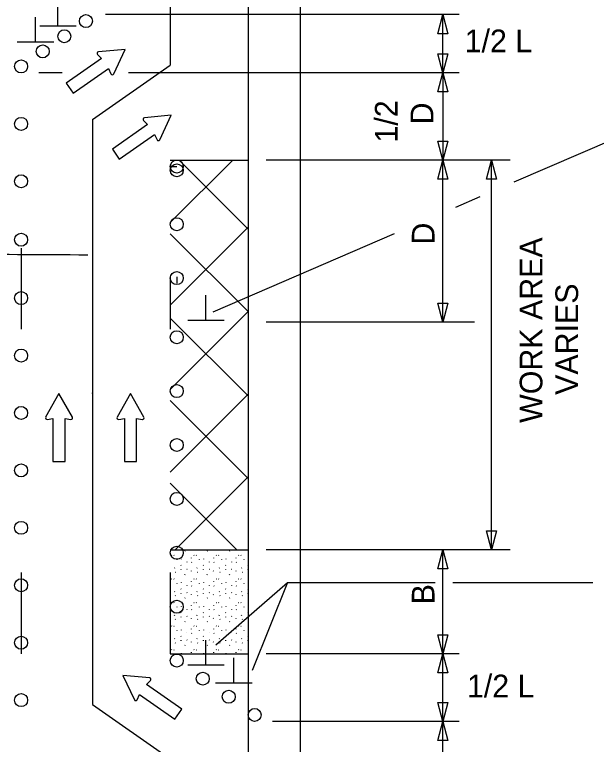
# Model space of a CAD drawing. Extents: x 16577 to 18475, y 5712 to 6919.
# Drawn here: x 16970.7 to 17150.1, y 6431 to 6656 of the extents above; entities that cross this region are included whole.
import ezdxf

# ---------------------------------------------------------------- set-up
doc = ezdxf.new("R2010")
doc.units = 0
for name, color, linetype in [('ALI_LEGAL_EX', 7, 'Continuous'), ('MT_SCRATCH_LEVEL_A', 7, 'Continuous'), ('MT_SCRATCH_LEVEL_E', 7, 'Continuous'), ('PAVT_EDGE_EX', 7, 'Continuous'), ('TRAFFIC_SIGNS_PR', 7, 'Continuous'), ('TYPICAL_TEXT_DIMEN_PR', 7, 'Continuous')]:
    doc.layers.add(name, color=color, linetype=linetype)

msp = doc.modelspace()

# ---------------------------------------------------------------- linework, layer by layer
at = {"layer": 'ALI_LEGAL_EX'}
for points in [[(16972.75, 6583.94), (16972.75, 6558.94)], [(17018.75, 6575.12), (17018.75, 6558.94)], [(17020.75, 6575.12), (17020.75, 6573.12)], [(16972.75, 6483.94), (16972.75, 6458.94)], [(17018.75, 6483.94), (17018.75, 6458.94)]]:
    msp.add_lwpolyline(points, dxfattribs=at)
at = {"layer": 'MT_SCRATCH_LEVEL_A'}
for p, q in [((17018.75, 6611.12), (17042.75, 6611.12)), ((17018.75, 6591.85), (17038.01, 6611.12)), ((17042.75, 6589.86), (17021.49, 6611.12)), ((17018.75, 6609.12), (17020.75, 6609.12)), ((17018.75, 6566.4), (17042.75, 6590.4)), ((17042.75, 6564.4), (17018.75, 6588.4)), ((17018.75, 6540.4), (17042.75, 6564.4)), ((17042.75, 6538.4), (17018.75, 6562.4)), ((17018.75, 6514.94), (17042.75, 6538.94)), ((17042.75, 6512.95), (17018.75, 6536.95)), ((17020.21, 6490.94), (17042.75, 6513.49)), ((17039.3, 6490.94), (17018.75, 6511.49)), ((17018.75, 6490.94), (17042.75, 6490.94)), ((17023.23, 6490.59), (17023.28, 6490.7)), ((17030.11, 6490.59), (17030.17, 6490.7)), ((17037, 6490.59), (17037.05, 6490.7)), ((17019.12, 6489.35), (17019.17, 6489.27)), ((17019.86, 6489.32), (17019.91, 6489.24)), ((17025.25, 6488.39), (17025.3, 6488.51)), ((17026.01, 6489.35), (17026.06, 6489.27)), ((17026.75, 6489.32), (17026.8, 6489.24)), ((17032.13, 6488.39), (17032.19, 6488.51)), ((17032.9, 6489.35), (17032.95, 6489.27)), ((17033.64, 6489.32), (17033.69, 6489.24)), ((17039.02, 6488.39), (17039.07, 6488.51)), ((17039.78, 6489.35), (17039.84, 6489.27)), ((17040.52, 6489.32), (17040.57, 6489.24)), ((17020.73, 6487.94), (17020.78, 6487.86)), ((17022.01, 6486.2), (17022.06, 6486.13)), ((17022.18, 6488.09), (17022.23, 6488.21)), ((17023.8, 6487.26), (17023.85, 6487.19)), ((17025.33, 6487.12), (17025.38, 6487.05)), ((17027.62, 6487.94), (17027.67, 6487.86)), ((17028.89, 6486.2), (17028.94, 6486.13)), ((17029.06, 6488.09), (17029.12, 6488.21)), ((17030.68, 6487.26), (17030.74, 6487.19)), ((17032.21, 6487.12), (17032.26, 6487.05)), ((17034.5, 6487.94), (17034.56, 6487.86)), ((17035.78, 6486.2), (17035.83, 6486.13)), ((17035.95, 6488.09), (17036, 6488.21)), ((17037.57, 6487.26), (17037.62, 6487.19)), ((17039.1, 6487.12), (17039.15, 6487.05)), ((17041.39, 6487.94), (17041.44, 6487.86)), ((17042.67, 6486.2), (17042.72, 6486.13)), ((17020.08, 6485.33), (17020.13, 6485.45)), ((17020.27, 6484.13), (17020.32, 6484.06)), ((17022.05, 6484.8), (17022.1, 6484.92)), ((17023.85, 6485.05), (17023.9, 6484.98)), ((17025.13, 6484.48), (17025.14, 6484.36)), ((17026.97, 6485.33), (17027.02, 6485.45)), ((17027.16, 6484.13), (17027.21, 6484.06)), ((17028.94, 6484.8), (17028.99, 6484.92)), ((17030.73, 6485.05), (17030.78, 6484.98)), ((17032.01, 6484.48), (17032.03, 6484.36)), ((17033.85, 6485.33), (17033.91, 6485.45)), ((17034.04, 6484.13), (17034.1, 6484.06)), ((17035.82, 6484.8), (17035.88, 6484.92)), ((17037.62, 6485.05), (17037.67, 6484.98)), ((17038.9, 6484.48), (17038.91, 6484.36)), ((17040.74, 6485.33), (17040.8, 6485.45)), ((17040.93, 6484.13), (17040.98, 6484.06)), ((17042.71, 6484.8), (17042.76, 6484.92)), ((17019.12, 6482.06), (17019.17, 6481.99)), ((17019.86, 6482.03), (17019.91, 6481.96)), ((17023.23, 6483.3), (17023.28, 6483.42)), ((17026.01, 6482.06), (17026.06, 6481.99)), ((17026.75, 6482.03), (17026.8, 6481.96)), ((17030.11, 6483.3), (17030.17, 6483.42)), ((17032.9, 6482.06), (17032.95, 6481.99)), ((17033.64, 6482.03), (17033.69, 6481.96)), ((17037, 6483.3), (17037.05, 6483.42)), ((17039.78, 6482.06), (17039.84, 6481.99)), ((17040.52, 6482.03), (17040.57, 6481.96)), ((17020.73, 6480.65), (17020.78, 6480.58)), ((17022.18, 6480.81), (17022.23, 6480.92)), ((17023.8, 6479.98), (17023.85, 6479.9)), ((17025.25, 6481.1), (17025.3, 6481.22)), ((17025.33, 6479.84), (17025.38, 6479.76)), ((17027.62, 6480.65), (17027.67, 6480.58)), ((17029.06, 6480.81), (17029.12, 6480.92)), ((17030.68, 6479.98), (17030.74, 6479.9)), ((17032.13, 6481.1), (17032.19, 6481.22)), ((17032.21, 6479.84), (17032.26, 6479.76)), ((17034.5, 6480.65), (17034.56, 6480.58)), ((17035.95, 6480.81), (17036, 6480.92)), ((17037.57, 6479.98), (17037.62, 6479.9)), ((17039.02, 6481.1), (17039.07, 6481.22)), ((17039.1, 6479.84), (17039.15, 6479.76)), ((17041.39, 6480.65), (17041.44, 6480.58)), ((17020.08, 6478.05), (17020.13, 6478.16)), ((17022.01, 6478.92), (17022.06, 6478.84)), ((17022.05, 6477.52), (17022.1, 6477.64)), ((17023.85, 6477.77), (17023.9, 6477.69)), ((17025.13, 6477.19), (17025.14, 6477.08)), ((17026.97, 6478.05), (17027.02, 6478.16)), ((17028.89, 6478.92), (17028.94, 6478.84)), ((17028.94, 6477.52), (17028.99, 6477.64)), ((17030.73, 6477.77), (17030.78, 6477.69)), ((17032.01, 6477.19), (17032.03, 6477.08)), ((17033.85, 6478.05), (17033.91, 6478.16)), ((17035.78, 6478.92), (17035.83, 6478.84)), ((17035.82, 6477.52), (17035.88, 6477.64)), ((17037.62, 6477.77), (17037.67, 6477.69)), ((17038.9, 6477.19), (17038.91, 6477.08)), ((17040.74, 6478.05), (17040.8, 6478.16)), ((17042.67, 6478.92), (17042.72, 6478.84)), ((17042.71, 6477.52), (17042.76, 6477.64)), ((17020.27, 6476.85), (17020.32, 6476.77)), ((17023.23, 6476.02), (17023.28, 6476.13)), ((17027.16, 6476.85), (17027.21, 6476.77)), ((17030.11, 6476.02), (17030.17, 6476.13)), ((17034.04, 6476.85), (17034.1, 6476.77)), ((17037, 6476.02), (17037.05, 6476.13)), ((17040.93, 6476.85), (17040.98, 6476.77)), ((17019.12, 6474.78), (17019.17, 6474.7)), ((17019.86, 6474.75), (17019.91, 6474.67)), ((17020.73, 6473.37), (17020.78, 6473.29)), ((17022.18, 6473.52), (17022.23, 6473.64)), ((17023.8, 6472.69), (17023.85, 6472.62)), ((17025.25, 6473.82), (17025.3, 6473.94)), ((17025.33, 6472.55), (17025.38, 6472.48)), ((17026.01, 6474.78), (17026.06, 6474.7)), ((17026.75, 6474.75), (17026.8, 6474.67)), ((17027.62, 6473.37), (17027.67, 6473.29)), ((17029.06, 6473.52), (17029.12, 6473.64)), ((17030.68, 6472.69), (17030.74, 6472.62)), ((17032.13, 6473.82), (17032.19, 6473.94)), ((17032.21, 6472.55), (17032.26, 6472.48)), ((17032.9, 6474.78), (17032.95, 6474.7)), ((17033.64, 6474.75), (17033.69, 6474.67)), ((17034.5, 6473.37), (17034.56, 6473.29)), ((17035.95, 6473.52), (17036, 6473.64)), ((17037.57, 6472.69), (17037.62, 6472.62)), ((17039.02, 6473.82), (17039.07, 6473.94)), ((17039.1, 6472.55), (17039.15, 6472.48)), ((17039.78, 6474.78), (17039.84, 6474.7)), ((17040.52, 6474.75), (17040.57, 6474.67)), ((17041.39, 6473.37), (17041.44, 6473.29)), ((17020.08, 6470.76), (17020.13, 6470.88)), ((17022.01, 6471.63), (17022.06, 6471.56)), ((17022.05, 6470.23), (17022.1, 6470.35)), ((17023.85, 6470.48), (17023.9, 6470.41)), ((17026.97, 6470.76), (17027.02, 6470.88)), ((17028.89, 6471.63), (17028.94, 6471.56)), ((17028.94, 6470.23), (17028.99, 6470.35)), ((17030.73, 6470.48), (17030.78, 6470.41)), ((17033.85, 6470.76), (17033.91, 6470.88)), ((17035.78, 6471.63), (17035.83, 6471.56)), ((17035.82, 6470.23), (17035.88, 6470.35)), ((17037.62, 6470.48), (17037.67, 6470.41)), ((17040.74, 6470.76), (17040.8, 6470.88)), ((17042.67, 6471.63), (17042.72, 6471.56)), ((17042.71, 6470.23), (17042.76, 6470.35)), ((17020.27, 6469.57), (17020.32, 6469.49)), ((17023.23, 6468.73), (17023.28, 6468.85)), ((17025.13, 6469.91), (17025.14, 6469.79)), ((17027.16, 6469.57), (17027.21, 6469.49)), ((17030.11, 6468.73), (17030.17, 6468.85)), ((17032.01, 6469.91), (17032.03, 6469.79)), ((17034.04, 6469.57), (17034.1, 6469.49)), ((17037, 6468.73), (17037.05, 6468.85)), ((17038.9, 6469.91), (17038.91, 6469.79)), ((17040.93, 6469.57), (17040.98, 6469.49)), ((17019.12, 6467.49), (17019.17, 6467.42)), ((17019.86, 6467.47), (17019.91, 6467.39)), ((17020.73, 6466.09), (17020.78, 6466.01)), ((17022.18, 6466.24), (17022.23, 6466.35)), ((17025.25, 6466.53), (17025.3, 6466.65)), ((17026.01, 6467.49), (17026.06, 6467.42)), ((17026.75, 6467.47), (17026.8, 6467.39)), ((17027.62, 6466.09), (17027.67, 6466.01)), ((17029.06, 6466.24), (17029.12, 6466.35)), ((17032.13, 6466.53), (17032.19, 6466.65)), ((17032.9, 6467.49), (17032.95, 6467.42)), ((17033.64, 6467.47), (17033.69, 6467.39)), ((17034.5, 6466.09), (17034.56, 6466.01)), ((17035.95, 6466.24), (17036, 6466.35)), ((17039.02, 6466.53), (17039.07, 6466.65)), ((17039.78, 6467.49), (17039.84, 6467.42)), ((17040.52, 6467.47), (17040.57, 6467.39)), ((17041.39, 6466.09), (17041.44, 6466.01)), ((17020.08, 6463.48), (17020.13, 6463.6)), ((17022.01, 6464.35), (17022.06, 6464.27)), ((17023.8, 6465.41), (17023.85, 6465.33)), ((17025.33, 6465.27), (17025.38, 6465.19)), ((17026.97, 6463.48), (17027.02, 6463.6)), ((17028.89, 6464.35), (17028.94, 6464.27)), ((17030.68, 6465.41), (17030.74, 6465.33)), ((17032.21, 6465.27), (17032.26, 6465.19)), ((17033.85, 6463.48), (17033.91, 6463.6)), ((17035.78, 6464.35), (17035.83, 6464.27)), ((17037.57, 6465.41), (17037.62, 6465.33)), ((17039.1, 6465.27), (17039.15, 6465.19)), ((17040.74, 6463.48), (17040.8, 6463.6)), ((17042.67, 6464.35), (17042.72, 6464.27)), ((17020.27, 6462.28), (17020.32, 6462.2)), ((17022.05, 6462.95), (17022.1, 6463.07)), ((17023.23, 6461.45), (17023.28, 6461.56)), ((17023.85, 6463.2), (17023.9, 6463.12)), ((17025.13, 6462.62), (17025.14, 6462.51)), ((17027.16, 6462.28), (17027.21, 6462.2)), ((17028.94, 6462.95), (17028.99, 6463.07)), ((17030.11, 6461.45), (17030.17, 6461.56)), ((17030.73, 6463.2), (17030.78, 6463.12)), ((17032.01, 6462.62), (17032.03, 6462.51)), ((17034.04, 6462.28), (17034.1, 6462.2)), ((17035.82, 6462.95), (17035.88, 6463.07)), ((17037, 6461.45), (17037.05, 6461.56)), ((17037.62, 6463.2), (17037.67, 6463.12)), ((17038.9, 6462.62), (17038.91, 6462.51)), ((17040.93, 6462.28), (17040.98, 6462.2)), ((17042.71, 6462.95), (17042.76, 6463.07)), ((17019.12, 6460.21), (17019.17, 6460.13)), ((17019.86, 6460.18), (17019.91, 6460.1)), ((17022.18, 6458.95), (17022.23, 6459.07)), ((17025.25, 6459.25), (17025.3, 6459.37)), ((17026.01, 6460.21), (17026.06, 6460.13)), ((17026.75, 6460.18), (17026.8, 6460.1)), ((17029.06, 6458.95), (17029.12, 6459.07)), ((17032.13, 6459.25), (17032.19, 6459.37)), ((17032.9, 6460.21), (17032.95, 6460.13)), ((17033.64, 6460.18), (17033.69, 6460.1)), ((17035.95, 6458.95), (17036, 6459.07)), ((17039.02, 6459.25), (17039.07, 6459.37)), ((17039.78, 6460.21), (17039.84, 6460.13)), ((17040.52, 6460.18), (17040.57, 6460.1)), ((17018.75, 6458.89), (17042.75, 6458.89))]:
    msp.add_line(p, q, dxfattribs=at)
at = {"layer": 'MT_SCRATCH_LEVEL_E'}
for p, q in [((16996.28, 6643.67), (16997.56, 6642.4)), ((16996.28, 6643.67), (16997.56, 6642.4)), ((17004.86, 6645.23), (16996.57, 6644.46)), ((17004.86, 6645.23), (16996.57, 6644.46)), ((17001.3, 6637.69), (17004.86, 6645.23)), ((17001.3, 6637.69), (17004.86, 6645.23)), ((16997.56, 6642.4), (16986.69, 6634.8)), ((16997.56, 6642.4), (16986.69, 6634.8)), ((16988.83, 6631.74), (16999.7, 6639.33)), ((16988.83, 6631.74), (16999.7, 6639.33)), ((16999.7, 6639.33), (17000.46, 6637.69)), ((16999.7, 6639.33), (17000.46, 6637.69)), ((16986.69, 6634.8), (16988.83, 6631.74)), ((16986.69, 6634.8), (16988.83, 6631.74)), ((17010.48, 6623.35), (17011.75, 6622.07)), ((17010.48, 6623.35), (17011.75, 6622.07)), ((17019.05, 6624.91), (17010.76, 6624.14)), ((17019.05, 6624.91), (17010.76, 6624.14)), ((17015.49, 6617.37), (17019.05, 6624.91)), ((17015.49, 6617.37), (17019.05, 6624.91)), ((17011.75, 6622.07), (17000.89, 6614.48)), ((17011.75, 6622.07), (17000.89, 6614.48)), ((17003.03, 6611.41), (17013.9, 6619.01)), ((17003.03, 6611.41), (17013.9, 6619.01)), ((17013.9, 6619.01), (17014.66, 6617.37)), ((17013.9, 6619.01), (17014.66, 6617.37)), ((17000.89, 6614.48), (17003.03, 6611.41)), ((17000.89, 6614.48), (17003.03, 6611.41)), ((16984.43, 6539.11), (16980.32, 6531.87)), ((16984.43, 6539.11), (16980.32, 6531.87)), ((16988.58, 6531.87), (16984.43, 6539.11)), ((16988.58, 6531.87), (16984.43, 6539.11)), ((17006.47, 6539.11), (17002.36, 6531.87)), ((17006.47, 6539.11), (17002.36, 6531.87)), ((17010.61, 6531.87), (17006.47, 6539.11)), ((17010.61, 6531.87), (17006.47, 6539.11)), ((16980.8, 6531.18), (16982.58, 6531.5)), ((16980.8, 6531.18), (16982.58, 6531.5)), ((16982.58, 6531.5), (16982.58, 6518.24)), ((16982.58, 6531.5), (16982.58, 6518.24)), ((16986.32, 6518.24), (16986.32, 6531.5)), ((16986.32, 6531.5), (16988.1, 6531.18)), ((16986.32, 6518.24), (16986.32, 6531.5)), ((16986.32, 6531.5), (16988.1, 6531.18)), ((17002.84, 6531.18), (17004.62, 6531.5)), ((17002.84, 6531.18), (17004.62, 6531.5)), ((17004.62, 6531.5), (17004.62, 6518.24)), ((17004.62, 6531.5), (17004.62, 6518.24)), ((17008.36, 6518.24), (17008.36, 6531.5)), ((17008.36, 6531.5), (17010.13, 6531.18)), ((17008.36, 6518.24), (17008.36, 6531.5)), ((17008.36, 6531.5), (17010.13, 6531.18)), ((16982.58, 6518.24), (16986.32, 6518.24)), ((16982.58, 6518.24), (16986.32, 6518.24)), ((17004.62, 6518.24), (17008.36, 6518.24)), ((17004.62, 6518.24), (17008.36, 6518.24)), ((17004.08, 6452.25), (17007.66, 6444.74)), ((17012.39, 6451.51), (17004.08, 6452.25)), ((17004.08, 6452.25), (17007.66, 6444.74)), ((17012.39, 6451.51), (17004.08, 6452.25)), ((17011.4, 6449.45), (17012.67, 6450.72)), ((17011.4, 6449.45), (17012.67, 6450.72)), ((17022.27, 6441.86), (17011.4, 6449.45)), ((17022.27, 6441.86), (17011.4, 6449.45)), ((17008.5, 6444.74), (17009.26, 6446.38)), ((17008.5, 6444.74), (17009.26, 6446.38)), ((17009.26, 6446.38), (17020.12, 6438.79)), ((17009.26, 6446.38), (17020.12, 6438.79)), ((17020.12, 6438.79), (17022.27, 6441.86)), ((17020.12, 6438.79), (17022.27, 6441.86))]:
    msp.add_line(p, q, dxfattribs=at)
for centre, start, end in [((16996.62, 6644), 95.3561, 224.895), ((16996.62, 6644), 95.3561, 224.895), ((17000.88, 6637.9), 204.9674, 334.7043), ((17000.88, 6637.9), 204.9674, 334.7043), ((17010.81, 6623.67), 95.3561, 224.895), ((17010.81, 6623.67), 95.3561, 224.895), ((17015.07, 6617.57), 204.9674, 334.7043), ((17015.07, 6617.57), 204.9674, 334.7043), ((16980.73, 6531.64), 150.4248, 279.9638), ((16980.73, 6531.64), 150.4248, 279.9638), ((16988.17, 6531.64), 260.0362, 29.7731), ((16988.17, 6531.64), 260.0362, 29.7731), ((17002.76, 6531.64), 150.4248, 279.9638), ((17002.76, 6531.64), 150.4248, 279.9638), ((17010.2, 6531.64), 260.0362, 29.7731), ((17010.2, 6531.64), 260.0362, 29.7731), ((17012.34, 6451.04), 315.105, 84.8419), ((17012.34, 6451.04), 315.105, 84.8419), ((17008.08, 6444.94), 205.4936, 335.0326), ((17008.08, 6444.94), 205.4936, 335.0326)]:
    msp.add_arc(centre, 0.463, start, end, dxfattribs=at)
at = {"layer": 'PAVT_EDGE_EX'}
for p, q in [((17042.75, 6901.43), (17042.75, 6139.45)), ((17058.75, 6901.43), (17058.75, 6139.45)), ((17018.75, 6704.47), (17018.75, 6640.39)), ((16994.75, 6623.63), (17018.75, 6640.39)), ((16994.75, 6623.63), (16994.75, 6618.4)), ((16994.75, 6618.4), (16994.75, 6443.28)), ((16994.75, 6539.11), (16994.75, 6539.36)), ((16994.75, 6443.28), (17018.75, 6426.52))]:
    msp.add_line(p, q, dxfattribs=at)
at = {"layer": 'TRAFFIC_SIGNS_PR'}
for centre in [(16992.75, 6653.95), (16986.08, 6649.29), (16979.42, 6644.63), (16972.75, 6639.98), (16972.75, 6639.98), (16972.75, 6622.27), (17020.75, 6609.12), (17020.75, 6607.96), (16972.75, 6604.57), (17020.75, 6591.35), (16972.75, 6586.57), (17020.75, 6574.73), (16972.75, 6568.57), (17020.75, 6556.51), (16972.75, 6550.86), (17020.75, 6539.89), (16972.75, 6533.16), (17020.75, 6523.28), (16972.75, 6515.45), (17020.75, 6506.67), (16972.75, 6497.75), (17020.75, 6490.06), (16972.75, 6480.04), (17020.75, 6473.44), (16972.75, 6462.34), (17020.75, 6456.83), (17020.75, 6456.83), (17028.75, 6451.25), (16972.75, 6444.63), (17036.75, 6445.66), (17044.75, 6440.07)]:
    msp.add_circle(centre, 2, dxfattribs=at)
at = {"layer": 'TYPICAL_TEXT_DIMEN_PR'}
for p, q in [((16984.12, 6652.38), (16984.12, 6660.17)), ((16977.2, 6647.43), (16977.2, 6655.22)), ((17107.75, 6655.95), (16998.81, 6655.95)), ((17101.18, 6650.08), (17102.75, 6655.95)), ((17102.75, 6637.98), (17102.75, 6655.95)), ((17102.75, 6655.95), (17104.32, 6650.08)), ((16989.75, 6652.38), (16978.5, 6652.38)), ((17102.75, 6650.08), (17101.18, 6650.08)), ((17104.32, 6650.08), (17102.75, 6650.08)), ((16982.82, 6647.43), (16971.57, 6647.43)), ((17102.75, 6637.98), (17101.18, 6643.84)), ((17101.18, 6643.84), (17102.75, 6643.84)), ((17102.75, 6643.84), (17104.32, 6643.84)), ((17104.32, 6643.84), (17102.75, 6637.98)), ((16985.38, 6637.98), (16978.19, 6637.98)), ((17107.75, 6637.98), (17005.82, 6637.98)), ((17101.18, 6632.12), (17102.75, 6637.98)), ((17102.75, 6637.98), (17104.32, 6632.12)), ((17102.75, 6637.98), (17102.75, 6611.12)), ((17102.75, 6632.12), (17101.18, 6632.12)), ((17104.32, 6632.12), (17102.75, 6632.12)), ((17170.01, 6623.87), (17124.64, 6604.3)), ((17102.75, 6611.12), (17101.18, 6616.98)), ((17101.18, 6616.98), (17102.75, 6616.98)), ((17102.75, 6616.98), (17104.32, 6616.98)), ((17104.32, 6616.98), (17102.75, 6611.12)), ((17123.47, 6611.12), (17048.25, 6611.12)), ((17101.18, 6605.26), (17102.75, 6611.12)), ((17102.75, 6561.12), (17102.75, 6611.12)), ((17102.75, 6611.12), (17104.32, 6605.26)), ((17116.18, 6605.26), (17117.75, 6611.12)), ((17117.75, 6490.94), (17117.75, 6611.12)), ((17117.75, 6611.12), (17119.32, 6605.26)), ((17102.75, 6605.26), (17101.18, 6605.26)), ((17104.32, 6605.26), (17102.75, 6605.26)), ((17117.75, 6605.26), (17116.18, 6605.26)), ((17119.32, 6605.26), (17117.75, 6605.26)), ((17114.14, 6599.77), (17106.66, 6596.54)), ((17087.78, 6588.4), (17031.85, 6564.27)), ((17029.72, 6561.69), (17029.72, 6569.47)), ((17102.75, 6561.12), (17101.18, 6566.98)), ((17101.18, 6566.98), (17102.75, 6566.98)), ((17102.75, 6566.98), (17104.32, 6566.98)), ((17104.32, 6566.98), (17102.75, 6561.12)), ((17035.35, 6561.69), (17024.1, 6561.69)), ((17110.89, 6561.12), (17048.25, 6561.12)), ((17112.51, 6561.12), (17106.68, 6561.12)), ((17117.75, 6490.94), (17116.18, 6496.81)), ((17116.18, 6496.81), (17117.75, 6496.81)), ((17117.75, 6496.81), (17119.32, 6496.81)), ((17119.32, 6496.81), (17117.75, 6490.94)), ((17123.47, 6490.94), (17048.25, 6490.94)), ((17101.18, 6485.08), (17102.75, 6490.94)), ((17102.75, 6458.89), (17102.75, 6490.94)), ((17102.75, 6490.94), (17104.32, 6485.08)), ((17102.75, 6485.08), (17101.18, 6485.08)), ((17104.32, 6485.08), (17102.75, 6485.08)), ((17032.81, 6461.69), (17054.92, 6480.9)), ((17054.92, 6480.9), (17043.99, 6453.72)), ((17054.92, 6480.9), (17100.36, 6480.9)), ((17105.84, 6480.9), (17148.98, 6480.9)), ((17102.75, 6458.89), (17101.18, 6464.75)), ((17101.18, 6464.75), (17102.75, 6464.75)), ((17102.75, 6464.75), (17104.32, 6464.75)), ((17104.32, 6464.75), (17102.75, 6458.89)), ((17029.72, 6455.38), (17029.72, 6463.17)), ((17038.32, 6449.87), (17038.32, 6457.65)), ((17107.75, 6458.89), (17048.25, 6458.89)), ((17101.18, 6453.02), (17102.75, 6458.89)), ((17102.75, 6458.89), (17104.32, 6453.02)), ((17102.75, 6438.07), (17102.75, 6458.89)), ((17035.35, 6455.38), (17024.1, 6455.38)), ((17102.75, 6453.02), (17101.18, 6453.02)), ((17104.32, 6453.02), (17102.75, 6453.02)), ((17043.94, 6449.87), (17032.69, 6449.87)), ((17102.75, 6438.07), (17101.18, 6443.94)), ((17101.18, 6443.94), (17102.75, 6443.94)), ((17102.75, 6443.94), (17104.32, 6443.94)), ((17104.32, 6443.94), (17102.75, 6438.07)), ((17107.75, 6438.07), (17050.26, 6438.07)), ((17101.18, 6432.21), (17102.75, 6438.07)), ((17102.75, 6388.07), (17102.75, 6438.07)), ((17102.75, 6438.07), (17104.32, 6432.21)), ((17102.75, 6432.21), (17101.18, 6432.21)), ((17104.32, 6432.21), (17102.75, 6432.21))]:
    msp.add_line(p, q, dxfattribs=at)
msp.add_open_spline([(16993.34, 6581.84), (16908.56, 6581.84), (16908.56, 6589.72), (16944.52, 6589.72), (16944.52, 6595.87), (16896.23, 6595.87), (16892.29, 6595.87)], degree=2, dxfattribs=at)

# ---------------------------------------------------------------- texts
for p in [(17109.48, 6644.35), (17110.18, 6445.49)]:
    msp.add_text('1/2 L', height=7, dxfattribs=at).set_placement(p)
for s, p in [('1/2', (17088.82, 6616.53)), ('D', (17099.82, 6622.1)), ('D', (17100.19, 6585.07)), ('WORK AREA', (17133.45, 6530.09)), ('VARIES', (17144.45, 6538.73)), ('B', (17100.19, 6474.15))]:
    msp.add_text(s, height=7, rotation=90, dxfattribs=at).set_placement(p)

doc.saveas('drawing.dxf')
